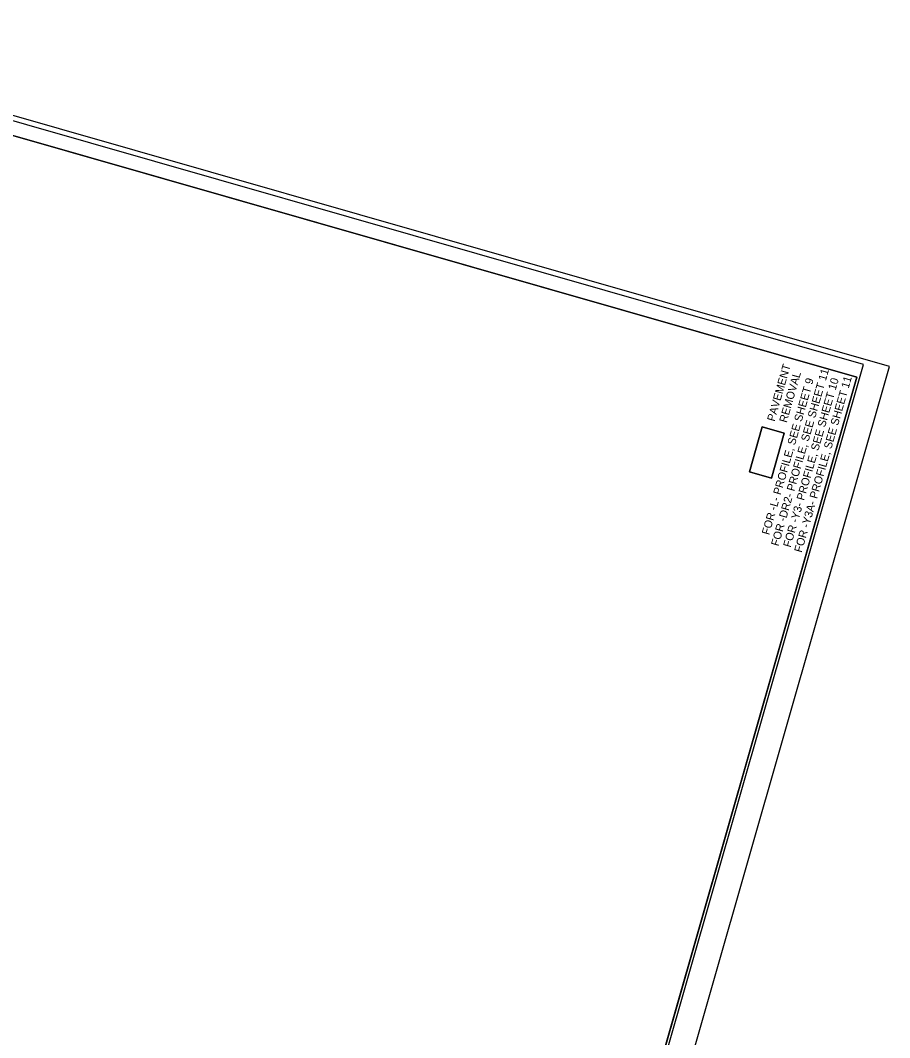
# Model space of a CAD drawing. Extents: x 2096988 to 2098509, y 687711 to 689775.
# Drawn here: x 2097748 to 2098509, y 688743 to 689632 of the extents above; entities that cross this region are included whole.
import ezdxf

# ---------------------------------------------------------------- set-up
doc = ezdxf.new("R2010")
doc.units = 0
for name, color, linetype in [('Default', 7, 'Continuous'), ('Prop Dimension Text', 7, 'Continuous'), ('Sheet Layout Plan Border', 7, 'Continuous'), ('Sheet Plot Border Inside CELL', 7, 'Continuous'), ('Sheet Plot Border Outside CELL', 7, 'Continuous'), ('Sheet Profile CELL', 7, 'Continuous')]:
    doc.layers.add(name, color=color, linetype=linetype)

msp = doc.modelspace()

# ---------------------------------------------------------------- linework, layer by layer
at = {"layer": 'Default'}
msp.add_lwpolyline([(2098405.33, 689232.05), (2098416.59, 689271.4), (2098397.32, 689276.92), (2098386.06, 689237.56), (2098405.33, 689232.05)], dxfattribs=at)
at = {"layer": 'Prop Dimension Text'}
msp.add_lwpolyline([(2098386.06, 689237.56), (2098397.32, 689276.92), (2098416.59, 689271.4), (2098405.33, 689232.05)], close=True, dxfattribs=at)
at = {"layer": 'Sheet Layout Plan Border'}
msp.add_lwpolyline([(2098117.8, 688054.49), (2097347.73, 688084.03), (2097057.83, 688167.01), (2097415.58, 689416.76), (2097595.66, 689365.22), (2097650.71, 689557.55), (2098480.09, 689320.13)], close=True, dxfattribs=at)
at = {"layer": 'Sheet Plot Border Inside CELL'}
msp.add_lwpolyline([(2098027.36, 687729.29), (2098485.98, 689331.44), (2097471.62, 689621.81), (2097013, 688019.66)], close=True, dxfattribs=at)
at = {"layer": 'Sheet Plot Border Outside CELL'}
msp.add_lwpolyline([(2098045.36, 687710.62), (2098508.8, 689329.59), (2097451.28, 689632.31), (2096987.84, 688013.34)], close=True, dxfattribs=at)
at = {"layer": 'Sheet Profile CELL'}
msp.add_line((2098067.29, 687878.05), (2098480.09, 689320.13), dxfattribs=at)
msp.add_lwpolyline([(2097470.64, 689609.09), (2097057.83, 688167.01), (2098067.29, 687878.05), (2098480.09, 689320.13)], close=True, dxfattribs=at)

# ---------------------------------------------------------------- texts
at = {"layer": 'Prop Dimension Text'}
for s, p in [('PAVEMENT', (2098408.11, 689281.07)), ('FOR -L- PROFILE, SEE SHEET 9', (2098403.44, 689181.81)), ('FOR -DR2- PROFILE, SEE SHEET 11', (2098411.56, 689172.02)), ('REMOVAL', (2098418.73, 689279.99)), ('FOR -Y3- PROFILE, SEE SHEET 10', (2098422.17, 689170.92)), ('FOR -Y3A- PROFILE, SEE SHEET 11', (2098431.81, 689166.44))]:
    msp.add_text(s, height=7, rotation=74.02589, dxfattribs=at).set_placement(p)

doc.saveas('drawing.dxf')
